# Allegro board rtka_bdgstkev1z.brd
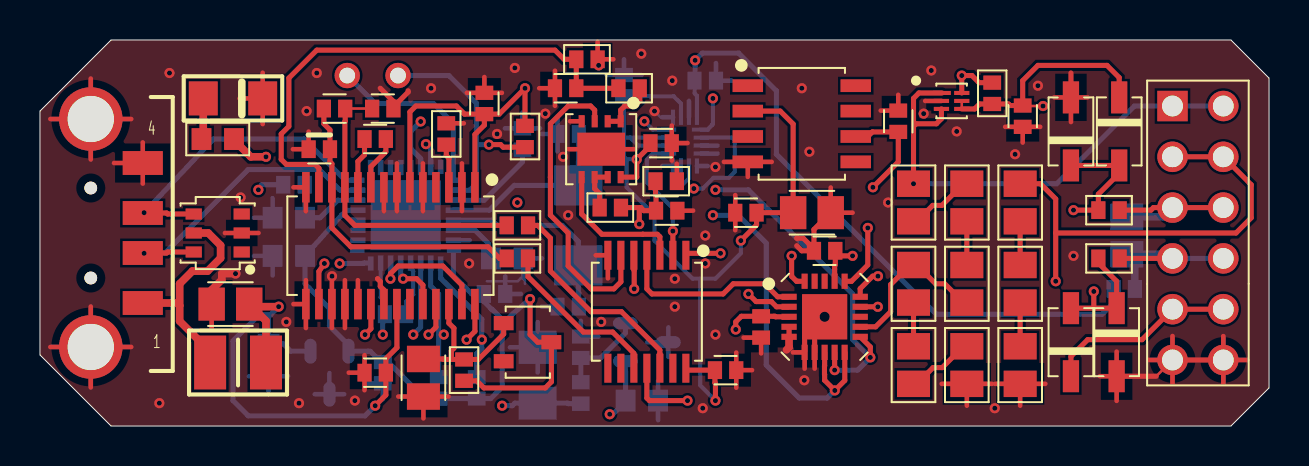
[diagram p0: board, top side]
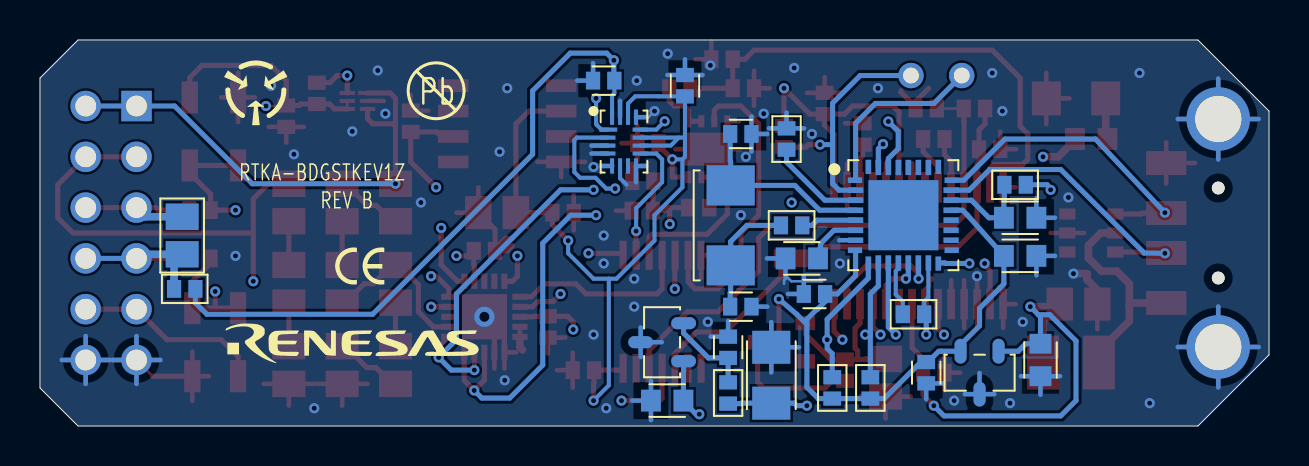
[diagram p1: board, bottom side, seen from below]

Outline 61.47 x 19.3 mm; copper layers: TOP, LAYER2, LAYER3, BOTTOM. Coordinates in mm from the lower left corner of the outline.
Outline path: 0,15.75 3.56,19.3 59.56,19.3 61.47,17.4 61.47,1.91 59.56,0 3.56,0 0,3.56 0,15.75

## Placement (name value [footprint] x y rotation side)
C1  -  [CAP_0402]  22.23 16.13 90 top
C2  -  [CAP_0402]  16.76 14.35 0 top
C3  -  [CAP_0603]  30.1 1.27 0 bottom
C4  -  [CAP_1206]  24.89 2.54 90 bottom
C5  -  [CAP_0402]  27.05 3.94 90 bottom
C6  -  [CAP_0402]  16.76 2.67 180 top
C7  -  [CAP_0805]  9.52 6.1 180 top
C8  -  [CAP_0805]  19.18 2.41 270 top
C9  -  [CAP_0402]  26.42 14.61 180 bottom
C11  -  [CAP_0603]  12.45 10.41 0 bottom
C12  -  [CAP_0603]  23.37 8.38 0 bottom
C13  -  [CAP_0402]  26.42 5.97 180 bottom
C14  -  [CAP_0402]  22.73 6.6 0 bottom
C15  -  [CAP_0603]  12.45 8.51 0 bottom
C16  -  [CAP_0402]  26.29 16.89 180 top
C17  -  [CAP_0402]  33.27 17.27 0 bottom
C18  -  [CAP_0402]  31.34 10.77 0 top
C19  -  [CAP_0402]  31.06 14.15 0 top
C20  -  [CAP_0402]  29.21 17.02 90 bottom
C21  -  [CAP_0805]  38.61 10.67 0 top
C22  -  [CAP_0402]  35.31 10.67 180 top
C23  -  [CAP_0402]  42.93 15.24 90 top
C25  -  [CAP_0402]  39.24 8.76 180 top
C26  -  [CAP_0603]  11.43 3.3 270 bottom
C27  -  [CAP_0402]  34.29 2.79 0 top
C28  -  [CAP_0402]  17.14 15.88 0 top
C29  -  [CAP_0402]  14.73 15.88 180 top
C30  -  [CAP_0402]  13.97 13.84 180 top
C31  -  [CAP_0402]  17.14 2.67 270 bottom
C32  -  [CAP_0402]  49.15 15.49 270 top
D1  -  [SOT23]  24.38 4.19 270 top
D2  -  [SOD123]  53.85 4.19 270 top
D3  -  [DIA_LED1206]  9.65 16.38 0 top
D4  -  [SOD123]  51.56 14.73 90 top
D5  -  [SOD123]  51.56 4.19 90 top
D6  -  [SOD123]  53.97 14.73 270 top
J1  -  [CON_USB_MOLEX_480371000]  2.54 9.65 180 top
J2  -  [CON_HDR_90151-3X12]  56.64 16 0 top
L1  -  [SM1210]  9.91 3.18 0 top
NOREF  -  []  -16.42 15.65 90 top
NOREF#2  -  []  27.15 8.12 0 top
NOREF#3  -  []  33.11 8.31 90 top
NOREF#4  -  []  29.76 11.47 0 top
NOREF#5  -  []  -12.83 34.42 0 top
NOREF#6  -  []  16.54 12.96 0 top
NOREF#7  -  []  -383.16 -115.32 0 top
NOREF#8  -  []  70.1 0 90 top
NOREF#9  -  []  28.15 8.22 0 top
NOREF#10  -  []  31.65 2.89 0 top
NOREF#11  -  []  26.92 8.03 90 top
NOREF#12  -  []  29.76 8.37 90 top
NOREF#13  -  []  28.15 3.21 90 top
NOREF#14  -  []  67.82 34.42 0 top
NOREF#15  -  []  -12.83 -4.95 0 top
NOREF#16  -  []  32.3 2.89 90 top
NOREF#17  -  []  28.11 11.51 0 top
NOREF#18  -  []  7.69 8.7 0 top
NOREF#19  -  []  20.71 8.79 90 top
NOREF#20  -  []  15.8 13.71 0 top
NOREF#21  -  []  15.9 11.29 90 top
NOREF#22  -  []  15.34 8.04 90 top
NOREF#23  -  []  64.52 17.4 90 top
NOREF#24  -  []  0 21.21 0 top
NOREF#25  -  []  7.69 8.7 90 top
NOREF#26  -  []  41.66 16.76 180 bottom
NOREF#27  -  []  50.67 16.76 180 bottom
NOREF#28  -  []  45.47 8 180 bottom
NOREF#29  -  []  52.45 3.05 180 bottom
P1  -  [PAD-50]  15.37 17.53 180 bottom
P2  -  [PAD-50]  17.91 17.53 180 bottom
R1  -  [RES_0402]  20.32 14.61 270 top
R2  -  [RES_0402]  27.05 1.65 270 bottom
R3  -  [RES_0402]  21.21 2.79 270 top
R4  -  [RES_0402]  23.88 10.03 180 top
R5  -  [RES_0402]  23.88 8.38 180 top
R6  -  [RES_0402]  36.07 4.95 90 top
R7  -  [RES_0402]  12.7 12.07 0 bottom
R8  -  [RES_0402]  24.26 14.48 270 top
R9  -  [RES_0402]  24.13 14.35 270 bottom
R10  -  [RES_0402]  23.88 10.03 180 bottom
R11  -  [RES_0402]  17.78 5.59 180 bottom
R12  -  [RES_0402]  19.94 1.91 270 bottom
R13  -  [RES_0402]  21.84 1.91 270 bottom
R14  -  [RES_0402]  29.46 16.89 0 top
R15  -  [RES_0402]  28.52 10.92 0 top
R16  -  [RES_0805]  43.69 11.18 90 top
R17  -  [RES_0603]  8.89 14.35 0 top
R18  -  [RES_0805]  46.35 11.18 90 top
R19  -  [RES_0805]  46.35 7.11 90 top
R20  -  [RES_0402]  47.62 16.64 270 top
R21  -  [RES_0805]  54.36 9.53 90 bottom
R22  -  [RES_0805]  43.69 7.11 90 top
R23  -  [RES_0805]  43.69 3.05 90 top
R24  -  [RES_0805]  46.35 3.05 90 top
R25  -  [RES_0805]  49.02 11.18 90 top
R26  -  [RES_0805]  49.02 7.11 90 top
R27  -  [RES_0805]  49.02 3.05 90 top
R28  -  [RES_0402]  53.47 10.79 0 top
R29  -  [RES_0402]  53.47 8.38 0 top
R30  -  [RES_0402]  54.23 6.86 180 bottom
RC16  -  [RES_0402]  27.36 18.34 180 top
RC18  -  [RES_0402]  31.32 12.24 180 top
U1  -  [UTQFN16_102X71_157]  32.26 14.22 180 bottom
U2  -  [SOT23-3]  30.35 4.19 90 bottom
U3  -  [DFN8_118X118_256_EP2]  28.07 13.84 270 top
U4  -  [TSSOP14_173_256_V2]  30.35 5.72 270 top
U5  -  [QFN20_157X157_197_EP]  39.24 5.46 0 top
U6  -  [SOIC8_150_50E]  38.1 15.11 0 top
U7  -  [QFN32_197X197_197_EPA2]  18.29 10.54 180 bottom
U8  -  [SOT457]  8.89 9.65 180 top
U9  -  [SOT23-3]  14.48 2.67 0 bottom
U10  -  [TSSOP28_173_256]  17.53 9.02 270 top
U11  -  [UTDFN6_47X39_157_A]  45.59 16.26 0 top
Y1  -  [XTAL_NX5032GA]  26.92 10.03 270 bottom

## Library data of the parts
C1 C6 C25 = SM_CAP: User Part Number: CAP_0402; alternate symbols: (SM0402_DELTA,SM0402RF,SM0402RD,SMC_C_0402); part number: SM_CAP_0402-H1044-00103-16V10,0.01UF,16V,10%,CAP_0402
C2 C5 C14 C16-C20 C22 C23 C27-C32 = SM_CAP: User Part Number: CAP_0402; alternate symbols: (SM0402_DELTA,SM0402RF,SM0402RD,SMC_C_0402); part number: SM_CAP_0402-H1044-00104-16V10,0.1UF,16V,10%,CAP_0402
C3 C11 C12 C26 = SM_CAP: User Part Number: CAP_0603; alternate symbols: (SM0603_DELTA,SM0603RF,SM0603RD,SMC_C_0603); part number: SM_CAP_0603-H1045-00105-16V20,1UF,16V,20%,CAP_0603
C4 = SM_CAP: User Part Number: CAP_1206; alternate symbols: (SM1206_DELTA,N_C1206,SM1206RF); part number: SM_CAP_1206-H1065-00106-16V10,10UF,16V,10%,CAP_1206
C7 = SM_CAP: User Part Number: CAP_0805; alternate symbols: (SM0805_DELTA,SM0805RF,SMC_C_0805); part number: SM_CAP_0805-GRM21BR71C475KA73L,4.7UF,16V,10%,CAP_0805
C8 = SM_CAP: User Part Number: CAP_0805; alternate symbols: (SM0805_DELTA,SM0805RF,SMC_C_0805); part number: SM_CAP_0805-H1046-00225-16V10,2.2UF,16V,10%,CAP_0805
C9 C13 = SM_CAP: User Part Number: CAP_0402; alternate symbols: (SM0402_DELTA,SM0402RF,SM0402RD,SMC_C_0402); part number: SM_CAP_0402-H1044-00100-50V10,10PF,50V,10%,CAP_0402
C15 = SM_CAP: User Part Number: CAP_0603; alternate symbols: (SM0603_DELTA,SM0603RF,SM0603RD,SMC_C_0603); part number: SM_CAP_0603-H1045-00334-25V10,0.33UF,25V,10%,CAP_0603
C21 = SM_CAP: User Part Number: CAP_0805; alternate symbols: (SM0805_DELTA,SM0805RF,SMC_C_0805); part number: SM_CAP_0805-C0805C106K8PACTU,10UF,10V,10%,CAP_0805
D1 = SM_SCHOTTKY: User Part Number: SOT23; part number: SM_SCHOTTKY_SINGLE-BAT54,SOT23
D2 D4-D6 = MMSD4148T1: User Part Number: SOD123; part number: MMSD4148T1_SOD123-MMSD4148T1,SOD123
D3 = SM_LED: User Part Number: DIA_LED1206; part number: SM_LED_SMD-597-3311-407,DIA_LED1206
J1 = USB_A: User Part Number: CON_USB_MOLEX_480371000; alternate symbols: (CON_USB_MOLEX_480371000_VER2,CON_USB_MOLEX_480371000); part number: USB_A_MOLEX1-48037-1000,CON_USB_MOLEX_480371000
J2 = HEADERS: User Part Number: CON_HDR_90151-3X12; part number: HEADERS_12-90151-3X12,CON_HDR_90151-3X12
L1 = IND1210: User Part Number: SM1210; part number: IND1210_SMD-IND1210-TBD,TBD,TBD,TBD,SM1210
P1 P2 = SINGLE: part number: SINGLE_THOLE-PAD_50-DNP,PAD-50
R1 R6 R11 R30 = SM_RES: User Part Number: RES_0402; part number: SM_RES_0402-H2510-00R00-1/16W,0,1/16W,0%,RES_0402
R2 R7 = SM_RES: User Part Number: RES_0402; part number: SM_RES_0402-H2510-01000-1/16W1,100,1/16W,1%,RES_0402
R3 = SM_RES: User Part Number: RES_0402; part number: SM_RES_0402-H2510-01001-1/16W1,1K,1/16W,1%,RES_0402
R4 R5 R14 R15 = SM_RES: User Part Number: RES_0402; part number: SM_RES_0402-H2510-049R9-1/16W1,49.9,1/16W,1%,RES_0402
R8 R9 R28 R29 = SM_RES: User Part Number: RES_0402; part number: SM_RES_0402-H2510-01002-1/16W1,10K,1/16W,1%,RES_0402
R10 = SM_RES: User Part Number: RES_0402; part number: SM_RES_0402-H2510-02210-1/16W1,221,1/16W,1%,RES_0402
R12 R13 R20 RC16 RC18 = SM_RES: User Part Number: RES_0402; part number: SM_RES_0402-H2510-04991-1/16W1,4.99K,1/16W,1%,RES_0402
R16 R22 R25 = SM_RES: User Part Number: RES_0805; part number: SM_RES_0805-H2512-02490-1/10W1,249,1/10W,1%,RES_0805
R17 = SM_RES: User Part Number: RES_0603; part number: SM_RES_0603-MCR03EZPFX3001,3K,1/10W,1%,RES_0603
R18 R23 R26 = SM_RES: User Part Number: RES_0805; part number: SM_RES_0805-H2512-01000-1/10W1,100,1/10W,1%,RES_0805
R19 R24 R27 = SM_RES: User Part Number: RES_0805; part number: SM_RES_0805-H2512-00010-1/10W1,1,1/10W,1%,RES_0805
R21 = SM_RES: User Part Number: RES_0805; part number: SM_RES_0805-H2512-04990-1/10W1,499,1/10W,1%,RES_0805
U1 = ISL23328: User Part Number: UTQFN16_102x71_157; part number: ISL23328_UTQFN16-ISL23328TFRUZ,UTQFN16_102X71_157
U2 = ISL21010: User Part Number: SOT23-3; part number: ISL21010_SOT23-3-ISL21010CFH341Z-TK,SOT23-3
U3 = ISL28233: User Part Number: DFN8_118X118_256_EP2; part number: ISL28233_TDFN8-ISL28233FRZ,DFN8_118X118_256_EP2
U4 = ISL28634: User Part Number: TSSOP14_173_256_V2; part number: ISL28634_TSSOP14-ISL28634FVZ,TSSOP14_173_256_V2
U5 = ISL43840: User Part Number: QFN20_157X157_197_EP; part number: ISL43840_20QFN-ISL43840IRZ,QFN20_157X157_197_EP
U6 = ISL21090: User Part Number: SOIC8_150_50E; part number: ISL21090_SOIC8-ISL21090BFB825Z-TK,SOIC8_150_50E
U7 = R5F10JBCANA: User Part Number: QFN32_197X197_197_EPA2; part number: R5F10JBCANA_32HWQFN-R5F10JBCANA,QFN32_197X197_197_EPA2
U8 = IP4220CZ6: User Part Number: SOT457; part number: IP4220CZ6_SOT457-IP4220CZ6,SOT457
U9 = ISL21010: User Part Number: SOT23-3; part number: ISL21010_SOT23-3-ISL21010CFH333Z-TK,SOT23-3
U10 = ISL26104: User Part Number: TSSOP28_173_256; part number: ISL26104_TSSOP-ISL26104AVZ,TSSOP28_173_256
U11 = ISL54054: User Part Number: UTDFN6_47X39_157_A; part number: ISL54054_UTDFN6-ISL54054IRUZ,UTDFN6_47X39_157_A
Y1 = SM_CRYSTAL: User Part Number: XTAL_NX5032GA; part number: SM_CRYSTAL_SM-NX5032GA-48.000M-LN-CD-1,XTAL_NX5032GA

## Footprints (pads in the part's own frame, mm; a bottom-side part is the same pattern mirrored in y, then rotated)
CAP_0402
  rect 0.711x0.889 smd: 1(-0.533,0) 2(0.533,0)
CAP_0603
  rect 0.991x1.092 smd: 1(-0.813,0) 2(0.813,0)
CAP_0805
  rect 1.321x1.651 smd: 1(-0.94,0) 2(0.94,0)
CAP_1206
  rect 1.651x1.905 smd: 1(-1.397,0) 2(1.397,0)
CON_HDR_90151-3X12
  rect 1.524x1.524 hole 1.041: 1(0,0)
  round 1.524 hole 1.041: 2(2.54,0) 3(0,-2.54) 4(2.54,-2.54) 5(0,-5.08) 6(2.54,-5.08) 7(0,-7.62) 8(2.54,-7.62) 9(0,-10.16) 10(2.54,-10.16) 11(0,-12.7) 12(2.54,-12.7)
CON_USB_MOLEX_480371000
  round 0.635 hole 1.194 unplated: (0,2.25) (0,-2.25)
  rect 2.007x1.194 smd: 1(-2.6,3.5) 2(-2.6,1) 3(-2.6,-1) 4(-2.6,-3.5)
  round 3.175 hole 2.311: M1(0,5.7) M2(0,-5.7)
DFN8_118X118_256_EP2
  rect 0.61x0.305 smd: 1(-1.397,0.975) 2(-1.397,0.325) 3(-1.397,-0.325) 4(-1.397,-0.975) 5(1.397,-0.975) 6(1.397,-0.325) 7(1.397,0.325) 8(1.397,0.975)
  rect 1.651x2.388 smd: 9(0,0)
DIA_LED1206
  rect 1.448x1.702 smd: 1(-1.486,0) 2(1.486,0)
PAD-50
  round 1.27 hole 0.787: 1(0,0)
QFN20_157X157_197_EP
  rect 0.762x0.305 smd: 1(-1.778,1.001) 2(-1.778,0.5) 3(-1.778,0) 4(-1.778,-0.5) 5(-1.778,-1.001) 11(1.778,-1.001) 12(1.778,-0.5) 13(1.778,0) 14(1.778,0.5) 15(1.778,1.001)
  rect 0.305x0.762 smd: 6(-1.001,-1.778) 7(-0.5,-1.778) 8(0,-1.778) 9(0.5,-1.778) 10(1.001,-1.778) 16(1.001,1.778) 17(0.5,1.778) 18(0,1.778) 19(-0.5,1.778) 20(-1.001,1.778)
  rect 2.261x2.261 smd: 21(0,0)
QFN32_197X197_197_EPA2
  rect 0.711x0.279 smd: 1(-2.418,1.75) 8(-2.418,-1.75) 17(2.418,-1.75) 24(2.418,1.75)
  rect 0.762x0.279 smd: 2(-2.388,1.252) 3(-2.388,0.752) 4(-2.388,0.249) 5(-2.388,-0.249) 6(-2.388,-0.752) 7(-2.388,-1.252) 18(2.388,-1.252) 19(2.388,-0.752) 20(2.388,-0.249) 21(2.388,0.249) 22(2.388,0.752) 23(2.388,1.252)
  rect 0.279x0.711 smd: 9(-1.75,-2.418) 16(1.75,-2.418) 25(1.75,2.418) 32(-1.75,2.418)
  rect 0.279x0.762 smd: 10(-1.252,-2.388) 11(-0.752,-2.388) 12(-0.249,-2.388) 13(0.249,-2.388) 14(0.752,-2.388) 15(1.252,-2.388) 26(1.252,2.388) 27(0.752,2.388) 28(0.249,2.388) 29(-0.249,2.388) 30(-0.752,2.388) 31(-1.252,2.388)
  rect 3.505x3.505 smd: 33(0,0)
RES_0402
  rect 0.711x0.889 smd: 1(-0.533,0) 2(0.533,0)
RES_0603
  rect 0.991x1.092 smd: 1(-0.813,0) 2(0.813,0)
RES_0805
  rect 1.321x1.651 smd: 1(-0.94,0) 2(0.94,0)
SM1210
  rect 1.6x2.692 smd: 1(-1.397,0) 2(1.397,0)
SOD123
  rect 1.6x0.813 smd: 1(-1.702,0) 2(1.702,0)
SOIC8_150_50E
  rect 1.524x0.635 smd: 1(-2.7,1.905) 2(-2.7,0.635) 3(-2.7,-0.635) 4(-2.7,-1.905) 5(2.7,-1.905) 6(2.7,-0.635) 7(2.7,0.635) 8(2.7,1.905)
SOT23
  rect 0.711x0.991 smd: 1(-0.953,-1.194) 2(0.953,-1.194) 3(0,1.194)
SOT23-3
  oval 0.61x1.245 smd: 1(-0.95,-1.075) 2(0.95,-1.075) 3(0,1.075)
SOT457
  rect 0.813x0.559 smd: 1(-1.2,0.95) 2(-1.2,0) 3(-1.2,-0.95) 4(1.2,-0.95) 5(1.2,0) 6(1.2,0.95)
TSSOP14_173_256_V2
  rect 1.448x0.356 smd: 1(-2.825,1.95) 2(-2.825,1.3) 3(-2.825,0.65) 4(-2.825,0) 5(-2.825,-0.65) 6(-2.825,-1.3) 7(-2.825,-1.95) 8(2.825,-1.95) 9(2.825,-1.3) 10(2.825,-0.65) 11(2.825,0) 12(2.825,0.65) 13(2.825,1.3) 14(2.825,1.95)
TSSOP28_173_256
  rect 1.524x0.381 smd: 1(-2.921,4.227) 2(-2.921,3.576) 3(-2.921,2.926) 4(-2.921,2.276) 5(-2.921,1.626) 6(-2.921,0.975) 7(-2.921,0.325) 8(-2.921,-0.325) 9(-2.921,-0.975) 10(-2.921,-1.626) 11(-2.921,-2.276) 12(-2.921,-2.926) 13(-2.921,-3.576) 14(-2.921,-4.227) 15(2.921,-4.227) 16(2.921,-3.576) 17(2.921,-2.926) 18(2.921,-2.276) 19(2.921,-1.626) 20(2.921,-0.975) 21(2.921,-0.325) 22(2.921,0.325) 23(2.921,0.975) 24(2.921,1.626) 25(2.921,2.276) 26(2.921,2.926) 27(2.921,3.576) 28(2.921,4.227)
UTDFN6_47X39_157_A
  rect 0.889x0.203 smd: 1(-0.483,0.399)
  rect 0.762x0.203 smd: 2(-0.508,0) 3(-0.508,-0.399) 4(0.508,-0.399) 5(0.508,0) 6(0.508,0.399)
UTQFN16_102X71_157
  rect 0.889x0.203 smd: 1(-0.787,0.598)
  rect 0.762x0.203 smd: 2(-0.813,0.199) 3(-0.813,-0.199) 4(-0.813,-0.598) 9(0.813,-0.598) 10(0.813,-0.199) 11(0.813,0.199) 12(0.813,0.598)
  rect 0.203x0.762 smd: 5(-0.598,-1.219) 6(-0.199,-1.219) 7(0.199,-1.219) 8(0.598,-1.219) 13(0.598,1.219) 14(0.199,1.219) 15(-0.199,1.219) 16(-0.598,1.219)
XTAL_NX5032GA
  rect 2.007x2.413 smd: 1(-2,0) 2(2,0)

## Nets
+3.3V: C1.1(A) C14.1(A) C15.2(B) C17.1(A) C31.1(A) D1.3(CATS) R3.2(B) R8.1(A) R12.2(B) R13.2(B) R30.2(B) U1.16 U7.8 U7.21 U9.2(VOUT) U10.1 U10.6
+5V: C3.1(A) C6.1(A) C7.1(A) C19.1(A) C20.1(A) C21.1(A) C22.1(A) C25.1(A) C26.1(A) C27.1(A) C32.1(A) D5.1(CAT) D6.1(CAT) J2.9(IN1) J2.10(IN1) L1.2(B) R7.1(A) R17.2(B) R20.2(B) U1.10 U1.11 U1.14 U2.1(VIN) U3.8 U4.14 U5.17 U6.2 U9.1(VIN) U10.22 U11.4 U11.5
GND: C1.2(B) C3.2(B) C4.2(B) C5.2(B) C6.2(B) C7.2(B) C8.2(B) C9.2(B) C11.1(A) C12.2(B) C13.2(B) C14.2(B) C15.1(A) C16.2(B) C17.2(B) C18.2(B) C19.2(B) C20.2(B) C21.2(B) C22.2(B) C23.2(B) C25.2(B) C26.2(B) C27.2(B) C28.2(B) C30.2(B) C31.2(B) C32.2(B) D2.2(AN) D3.2(B) D4.2(AN) J1.4 J1.M1 J1.M2 J2.11(IN1) J2.12(IN1) R1.1(A) R6.1(A) R9.1(A) R24.1(A) R27.1(A) RC16.1(A) RC18.1(A) U1.3 U1.4 U1.5 U1.6 U1.8 U1.13 U1.15 U2.3(GND) U3.4 U3.9(EP) U4.7 U5.4 U5.5 U5.6 U5.7 U5.21 U6.4 U7.7 U8.2 U9.3(GND) U10.2 U10.5 U10.7 U10.8 U10.14 U10.15 U10.17 U10.18 U10.19 U10.21 U11.2
ADDA: U5.8 U5.10 U7.31
ADDB: U5.9 U5.11 U7.30
CS: U7.13 U10.24
IN: R20.1(A) U7.11 U11.6
IN2: C16.1(A) R14.1(A) RC16.2(B) U10.13
IN3: C18.1(A) R15.2(B) RC18.2(B) U10.16
SCL: R13.1(A) U1.2 U7.9
SCLK: U7.14 U10.27
SDA: R12.1(A) U1.1 U7.10
SDI: U7.16 U10.25
SDO/RDY: R11.2(B) U7.15 U10.28
UNNAMED_1_1210IND_I97_A: J1.1 L1.1(A) U8.5
UNNAMED_1_HEADERS_I279_IN1: J2.1(IN1) J2.2(IN1) R16.2(B) U11.1 U11.3
UNNAMED_1_HEADERS_I281_IN1: J2.3(IN1) J2.4(IN1) R25.2(B) U5.2
UNNAMED_1_HEADERS_I283_IN1: J2.5(IN1) J2.6(IN1) R21.2(B) R28.2(B)
UNNAMED_1_HEADERS_I285_IN1: J2.7(IN1) J2.8(IN1) R21.1(A) R29.2(B) R30.1(A)
UNNAMED_1_IP4220CZ6_I167_4: J1.3 U7.24 U8.4
UNNAMED_1_IP4220CZ6_I167_6: J1.2 U7.23 U8.6
UNNAMED_1_ISL23328_I318_9: U1.9 U4.2
UNNAMED_1_ISL23328_I318_12: U1.12 U4.1
UNNAMED_1_ISL26104_I314_10: C2.1(A) U10.10
UNNAMED_1_ISL28233_I317_1: R14.2(B) U3.1 U3.2
UNNAMED_1_ISL28233_I317_3: U3.3 U4.6
UNNAMED_1_ISL28233_I317_5: U3.5 U4.3
UNNAMED_1_ISL28233_I317_6: R15.1(A) U3.6 U3.7
UNNAMED_1_ISL28634_I315_4: U4.4 U5.1
UNNAMED_1_ISL28634_I315_5: U4.5 U5.14
UNNAMED_1_ISL43840_I225_15: R6.2(B) U5.3 U5.15
UNNAMED_1_MMSD4148T1_I291_AN: D4.1(CAT) D6.2(AN) R28.1(A) U5.16
UNNAMED_1_MMSD4148T1_I302_CAT: D2.1(CAT) D5.2(AN) R29.1(A) U5.20
UNNAMED_1_R5F10JBCANA_I307_1: P1.1(P) U7.1
UNNAMED_1_R5F10JBCANA_I307_2: P2.1(P) R8.2(B) U7.2
UNNAMED_1_R5F10JBCANA_I307_3: R9.2(B) U7.3
UNNAMED_1_R5F10JBCANA_I307_5: R10.2(B) U7.5
UNNAMED_1_R5F10JBCANA_I307_6: C12.1(A) U7.6
UNNAMED_1_R5F10JBCANA_I307_12: R11.1(A) U7.12
UNNAMED_1_R5F10JBCANA_I307_22: C11.2(B) R7.2(B) U7.22
UNNAMED_1_SMCAP_I18_B: C2.2(B) U10.9
UNNAMED_1_SMCAP_I21_A: C8.1(A) D1.1(ANS) R3.1(A) U10.26
UNNAMED_1_SMCAP_I197_A: C4.1(A) R2.2(B) U10.20
UNNAMED_1_SMCAP_I319_A: C28.1(A) C29.1(A) R4.2(B) U10.11
UNNAMED_1_SMCAP_I319_B: C29.2(B) C30.1(A) R5.2(B) U10.12
UNNAMED_1_SMCAP_I323_A: C23.1(A) U4.11 U6.6
UNNAMED_1_SMCAP_I358_A: C9.1(A) U7.4 Y1.1(A)
UNNAMED_1_SMCAP_I359_A: C13.1(A) R10.1(A) Y1.2(B)
UNNAMED_1_SMLED_I99_A: D3.1(A) R17.1(A)
UNNAMED_1_SMRES_I15_B: R1.2(B) U10.3
UNNAMED_1_SMRES_I227_A: R5.1(A) U4.10
UNNAMED_1_SMRES_I228_A: R4.1(A) U4.12
UNNAMED_1_SMRES_I262_A: R18.1(A) R19.2(B)
UNNAMED_1_SMRES_I262_B: R16.1(A) R18.2(B)
UNNAMED_1_SMRES_I264_A: R19.1(A) R22.2(B) U5.12
UNNAMED_1_SMRES_I265_A: R22.1(A) R23.2(B)
UNNAMED_1_SMRES_I266_A: R23.1(A) R24.2(B)
UNNAMED_1_SMRES_I268_A: R25.1(A) R26.2(B)
UNNAMED_1_SMRES_I269_A: R26.1(A) R27.2(B)
VREF: C5.1(A) R2.1(A) U2.2(VOUT)

Pads without a net: D1 2; U1 7; U4 8 9 13; U5 13 18 19; U6 1 3 5 7 8; U7 17 18 19 20 25 26 27 28 29 32 33; U8 1 3; U10 4 23

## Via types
v1: diameter 0.508, hole 0.254, TOP to BOTTOM, 96 vias
v2: diameter 1.016, hole 0.508, TOP to BOTTOM, 1 via

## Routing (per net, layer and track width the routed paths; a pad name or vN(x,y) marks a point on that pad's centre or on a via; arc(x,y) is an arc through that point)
+3.3V: length 106.9
  TOP w0.254: C1.1 21.23,15.6 20.83,16 18.8,16 18.5,15.71 U10.6 ; C1.1 22.96,15.6 v1(24.26,16.89) R8.1 ; C1.1 22.23,15.05 21.75,14.58 U10.1 ; R3.2 21.84,2.26 22.2,1.91 25.27,1.91 25.58,2.21 D1.3 24.89,4.19 24.51,4.57 v1(24.51,6.35)
  LAYER3 w0.254: v1(32.77,18.29) 31.46,18.29 30.41,17.19 30.11,16.89 26.92,16.89 ; v1(24.51,6.35) 24.51,10.03 26.92,12.45 26.92,16.89 ; 26.92,16.89 v1(24.26,16.89)
  BOTTOM w0.127: 20.68,8.79 20.68,8.79 U7.8 ; U7.21 15.9,10.79
  BOTTOM w0.203: U1.16 32.86,16.52 32.74,16.64 C17.1
  BOTTOM w0.254: 23.11,5.08 23.62,5.59 v1(24.51,6.35) ; 23.11,5.08 23.11,1.94 22.54,1.37 R13.2 R12.2 19.24,1.37 17.41,3.2 C31.1 17.06,3.2 16.52,3.74 16.39,3.74 16.39,3.74 U9.2 15.43,4.06 14.48,5.01 14.48,5.89 13.46,6.9 13.26,7.11 C15.2 15.08,10.54 15.33,10.79 15.9,10.79 ; 23.11,5.08 23.11,5.33 22.61,5.84 22.58,5.84 22.2,6.22 C14.1 21.59,6.6 20.68,7.52 20.68,8.79 ; R30.2 53.7,6.16 53.12,5.59 44.83,5.59 36.83,13.59 36.83,16.76 34.95,18.65 33.13,18.65 v1(32.77,18.29) 32.77,17.3 C17.1
+5V: length 171.6
  TOP w0.127: U6.2 35.56,15.75 ; v1(50.16,16) 49.17,16 C32.1 ; 39.78,8.06 39.78,7.87 39.74,7.84 ; U4.14 32.3,2.79 ; U11.5 U11.4
  TOP w0.254: 35.56,15.75 37.02,15.75 37.67,15.1 C21.1 C22.1 35.84,10.06 v1(35.05,9.27) ; U11.4 46.74,15.86 46.99,16.1 R20.2 48.44,16.1 48.51,16.03 C32.1 49.15,17.27 49.91,18.03 53.37,18.03 53.97,17.42 D6.1 ; v1(33.78,1.27) 33.78,2.13 33.76,2.16 C27.1 32.3,2.79 ; C19.1 30.53,14.02 v1(29.84,13.34) 29.84,12.45 U3.8 ; v1(16.76,1.02) 17.3,1.55 C6.1 17.3,3.37 17.85,3.92 U10.22 ; v1(40.64,8.51) 40.03,8.51 C25.1 39.78,8.06 39.74,8.03 U5.17 ; D5.1 51.56,3.48 52.4,4.32 55.12,4.32 J2.9 J2.10
  TOP w0.381: 10.59,5.97 v1(11.94,5.97) ; 10.59,5.97 C7.1 ; 10.59,5.97 11.3,5.26 L1.2 ; R17.2 9.7,14.3 10.54,13.46 v1(11.3,13.46)
  LAYER2 w0.254: v1(16.76,1.02) 17.27,0.51 27.9,0.51 27.99,0.59 v1(28.49,0.59) 28.81,0.27 33.49,0.27 33.78,0.57 v1(33.78,1.27)
  LAYER3 w0.254: 47.68,13.51 55.35,5.84 J2.9 ; 47.68,13.51 42.67,8.51 ; 47.68,13.51 v1(50.16,16) ; 42.67,8.51 v1(40.64,8.51) ; 42.67,8.51 43.31,7.87 43.31,2.54 41.68,0.91 34.14,0.91 v1(33.78,1.27) ; v1(11.94,5.97) 11.94,8.76 10.92,9.78 v1(10.92,11.81) 11.3,12.19 v1(11.3,13.46)
  BOTTOM w0.203: 29.52,14.42 29.92,14.02 U1.10 ; 29.52,14.42 29.21,14.42 ; 29.52,14.42 U1.11 ; 29.34,13.34 29.34,11.94 30.73,10.54 30.73,9.27 32.64,7.37 33.02,7.37 ; 29.34,13.34 29.21,13.46 29.21,14.42 ; 29.34,13.34 v1(29.84,13.34) ; 33.02,7.37 33.02,2.03 v1(33.78,1.27) ; 33.02,7.37 33.78,7.37 35.05,8.64 v1(35.05,9.27) ; 29.21,14.42 C20.1 30.54,16.48 30.55,16.49 31.69,16.49 32.06,16.13 U1.14
  BOTTOM w0.254: v1(10.92,11.81) 11.09,12.07 R7.1 ; v1(28.49,0.59) 28.66,0.59 29.29,1.22 C3.1 29.29,2.74 29.28,2.75 U2.1 ; v1(16.76,1.02) 16.26,0.51 10.41,0.51 9.65,1.27 9.65,4.25 10.96,5.56 11.53,5.56 ; 11.53,5.56 11.43,5.46 C26.1 12.17,4.11 12.54,3.74 U9.1 ; 11.53,5.56 v1(11.94,5.97)
GND: length 254.7
  TOP w0.127: 55.83,2.49 J2.11
  TOP w0.229: D2.2 53.85,3.72 ; D2.2 53.01,2.49 ; D2.2 53.85,1.26 ; 25.76,16.01 C16.2 ; C16.2 24.97,16.89 ; C16.2 25.76,17.77 ; 15.25,7.29 U10.18 15.25,4.9 ; 27.89,19.22 RC16.1 28.68,18.34 ; J2.11 56.64,4.5 ; J2.11 55.45,3.3 ; J2.11 56.64,2.11 ; 13.3,4.9 U10.15 ; U10.15 12.68,6.1 ; U10.15 13.3,7.29 ; J1.M2 4.56,15.35 ; J1.M2 2.54,13.33 ; J1.M2 0.52,15.35 ; J1.M2 2.54,17.37 ; 35.4,12.46 U6.4 ; U6.4 34.21,13.21 ; U6.4 36.59,13.21 ; C1.2 23.1,16.66 ; C1.2 22.23,17.45 ; C1.2 21.35,16.66 ; 29.69,13.84 U3.9 26.44,13.84 ; 39.55,11.93 C21.2 40.64,10.67 ; 51.56,15.2 D4.2 ; D4.2 52.4,16.43 ; D4.2 50.72,16.43 ; 19.15,10.74 U10.5 19.15,13.13 ; 38.74,2.87 U5.7 ; C27.2 35.61,2.79 ; C27.2 34.82,3.67 ; C27.2 34.82,1.92 ; C32.2 50.03,14.96 ; C32.2 49.15,14.17 ; C32.2 48.27,14.96 ; R24.1 47.61,2.11 ; R24.1 45.1,2.11 ; R24.1 46.35,1.02 ; 31.6,13.27 C19.2 ; C19.2 31.6,15.02 ; C19.2 32.39,14.15 ; 12.65,13.84 C30.2 13.44,14.72 ; 59.18,2.11 J2.12 ; J2.12 60.38,3.3 ; J2.12 59.18,4.5 ; 14.6,7.29 U10.17 14.6,4.9 ; 44.27,16.26 U11.2 ; 2.54,1.93 J1.M1 ; J1.M1 4.56,3.95 ; J1.M1 2.54,5.97 ; J1.M1 0.52,3.95 ; 34.77,9.79 C22.2 34.77,11.54 ; J1.4 5.14,14.18 ; J1.4 5.14,12.12 ; J1.4 3.7,13.15 ; 16.23,1.79 C6.2 ; C6.2 15.44,2.67 ; C6.2 16.23,3.54 ; 38.24,2.87 U5.6 37.66,3.68 ; 13.3,10.74 U10.14 12.68,11.94 ; 26.51,15.24 U3.4 ; RC18.1 31.85,13.12 ; U10.19 15.9,7.29 ; 8.59,4.84 C7.2 ; C8.2 20.43,1.47 ; C8.2 19.18,0.38 ; C8.2 17.92,1.47 ; 35.19,4.42 R6.1 36.07,3.63 ; 42.05,15.77 C23.2 42.93,16.56 ; 21.1,10.74 U10.2 21.1,13.13 ; 49.02,1.02 R27.1 ; R27.1 47.76,2.11 ; R27.1 50.28,2.11 ; 17.85,10.74 U10.7 17.85,13.13 ; 27.79,8.54 U4.7 28.4,7.38 ; 9.25,9.65 U8.2 10.93,9.65 ; 17.2,10.74 U10.8 ; 11.14,15.1 D3.2 ; D3.2 9.98,16.38 ; D3.2 11.14,17.67 ; R1.1 21.2,15.14 ; C18.2 32.66,10.77
  TOP w0.254: 17.68,15.96 18.41,16.7 18.41,16.76 ; 17.68,15.96 17.68,16.23 17.02,16.89 ; 17.68,15.96 C28.2 ; U5.7 38.74,4.96 ; 38.74,4.96 v2(39.24,5.46) ; 38.74,4.96 38.24,4.46 U5.6 ; 16.88,7.37 16.88,7.36 17.02,7.23 17.02,6.98 17.2,6.8 U10.21 ; 38.71,8.85 C25.2 38.1,8.76 37.85,9.02 ; 38.71,8.85 38.17,9.39 37.86,9.39 37.85,9.4 ; 38.71,8.85 38.71,9.83 C21.2 ; U5.4 U5.5 ; J2.11 J2.12 ; D2.2 55.83,2.49 ; D4.2 51.56,17.65
  TOP w0.381: C7.2 8.59,6.81 9.09,7.32 9.09,7.62 v1(9.78,7.62) ; U5.5 37.46,3.94 37.34,3.81
  LAYER2 w0.229: 56.64,2.11 J2.11 ; J2.11 57.84,3.3 ; J2.11 55.45,3.3 ; J2.11 56.64,4.5 ; 59.18,2.11 J2.12 ; J2.12 60.38,3.3 ; J2.12 57.99,3.3 ; J2.12 59.18,4.5 ; 0.52,15.35 J1.M2 ; J1.M2 2.54,17.37 ; J1.M2 4.56,15.35 ; J1.M2 2.54,13.33 ; J1.M1 4.56,3.95 ; J1.M1 2.54,5.97 ; J1.M1 0.52,3.95 ; J1.M1 2.54,1.93
  LAYER3 w0.229: 57.99,3.3 J2.12 ; J2.12 60.38,3.3 ; J2.12 59.18,2.11 ; J2.12 59.18,4.5 ; J1.M1 2.54,5.97 ; J1.M1 2.54,1.93 ; J1.M1 0.52,3.95 ; J1.M1 4.56,3.95 ; J2.11 57.84,3.3 ; J2.11 56.64,4.5 ; J2.11 56.64,2.11 ; J2.11 55.45,3.3 ; J1.M2 4.56,15.35 ; J1.M2 2.54,13.33 ; J1.M2 0.52,15.35 ; J1.M2 2.54,17.37
  BOTTOM w0.127: 24.26,7.11 24.26,7.28 24.13,7.4 24.05,7.4 23.89,7.24 22.35,7.24 ; v1(30.73,15.75) 31.05,15.43 31.65,15.43 U1.13
  BOTTOM w0.203: 32.13,12.07 32.46,12.39 U1.6
  BOTTOM w0.229: U2.3 31.43,4.93 ; U2.3 30.37,4.19 ; U2.3 31.43,3.45 ; U7.7 21.49,9.29 ; 2.54,1.93 J1.M1 ; J1.M1 4.56,3.95 ; J1.M1 2.54,5.97 ; J1.M1 0.52,3.95 ; 23.27,7.48 C14.2 24.05,6.6 ; J2.11 56.64,4.5 ; J2.11 56.64,2.11 ; J2.11 55.45,3.3 ; J2.11 57.84,3.3 ; 2.54,13.33 J1.M2 ; J1.M2 2.54,17.37 ; J1.M2 4.56,15.35 ; J1.M2 0.52,15.35 ; 11.63,11.39 C11.1 10.71,10.41 ; U9.3 15.22,1.59 ; U9.3 14.48,2.65 ; U9.3 13.74,1.59 ; 10.71,8.51 C15.1 11.63,7.53 ; 23.51,3.94 C4.2 ; C4.2 24.89,2.68 ; C4.2 24.89,5.19 ; 24.18,7.4 C12.2 25.11,8.38 ; C3.2 31.84,1.27 ; C3.2 30.91,0.29 ; C3.2 30.91,2.25 ; 31.13,15.44 U1.13 ; 31.66,12.19 U1.8 31.13,13 ; 25.09,14.61 C9.2 ; C9.2 25.88,15.48 ; C9.2 25.88,13.73 ; U1.5 33.39,13 ; 27.93,4.47 C5.2 27.05,5.26 ; U1.4 33.88,13.63 ; 11.43,1.56 C26.2 ; C26.2 10.45,2.49 ; C26.2 12.41,2.49 ; 16.27,2.13 C31.2 17.14,1.35 ; 34.6,17.27 C17.2 33.81,18.15 ; C20.2 30.09,17.55 ; C20.2 29.21,18.34 ; C20.2 28.33,17.55 ; U1.15 32.46,16.26 ; U1.3 33.88,14.02 ; 23.25,14.88 R9.1 ; R9.1 24.13,15.67 ; R9.1 25.01,14.88 ; J2.12 60.38,3.3 ; J2.12 57.99,3.3 ; J2.12 59.18,4.5 ; J2.12 59.18,2.11 ; 25.09,5.97 C13.2
  vias: v1(5.97,1.14) v1(6.48,17.65) v1(10.03,11.43) v1(12.32,5.21) v1(12.95,1.14) v1(13.34,15.75) v1(13.84,17.65) v1(14.61,7.49) v1(15.75,1.27) v1(19.56,16.89) v1(21.46,8.13) v1(22.86,14.61) v1(23.75,17.91) v1(25.27,15.62) v1(26.16,13.46) v1(26.42,10.54) v1(27.94,18.03) v1(28.07,5.21) v1(30.07,18.62) v1(31.62,17.27) v1(31.75,7.37) v1(31.75,5.97) v1(33.15,0.89) v1(33.27,9.53) v1(33.27,8.13) v1(33.78,12.95) v1(33.78,4.57) v1(38.1,16.89) v1(38.23,2.29) v1(38.48,13.72) v1(42.42,11.18) v1(44.2,15.62) v1(44.58,17.78) v1(45.85,14.73) v1(47.75,0.89) v1(48.77,13.59) v1(49.91,17.02) v1(51.69,8.51)
ADDA: length 34.9
  TOP w0.254: U5.8 39.24,3.01 39.24,3 39.24,2.58 39.24,2.58 39.24,2.29 v1(39.75,1.78) 40.25,2.28 40.25,3.68 U5.10
  LAYER2 w0.254: v1(19.3,14.1) 20.7,12.7 25.53,12.7 27.33,10.9 33.3,10.9 v1(33.66,10.54)
  BOTTOM w0.127: U7.31 19.54,12.93
  BOTTOM w0.254: v1(19.3,14.1) 19.54,13.86 19.54,12.93 ; v1(33.66,10.54) 34.93,10.54 36.32,9.14 36.32,3.05 37.97,1.4 39.37,1.4 v1(39.75,1.78)
ADDB: length 35.6
  TOP w0.254: U5.9 v1(39.74,2.79) ; U5.11 41.53,3.95 v1(41.53,3.43)
  LAYER2 w0.254: v1(19.04,15.23) 24.4,15.23 25.65,13.97 31.62,13.97 v1(33.78,11.81)
  BOTTOM w0.127: 19.04,12.93 U7.30
  BOTTOM w0.254: 19.04,12.93 19.04,13.37 18.54,13.87 18.54,14.73 v1(19.04,15.23) ; v1(39.74,2.79) 40.89,2.79 v1(41.53,3.43) 40.64,4.32 40.64,6.6 35.43,11.81 v1(33.78,11.81)
CS: length 2.9
  TOP w0.254: U10.24 19.15,7.05 18.83,7.37 v1(18.16,7.37)
  BOTTOM w0.127: U7.13 18.04,8.15
  BOTTOM w0.254: 18.04,8.15 18.04,7.49 v1(18.16,7.37)
IN: length 40.8
  TOP w0.254: U11.6 v1(46.1,17.53) 46.61,17.53 46.96,17.17 R20.1
  LAYER2 w0.254: v1(46.1,17.53) 45.21,16.64 43.43,16.64 29.34,2.54 20.7,2.54 v1(18.67,4.57)
  BOTTOM w0.127: 19.04,8.15 U7.11
  BOTTOM w0.254: v1(18.67,4.57) 19.04,4.94 19.04,8.15
IN2: length 25.9
  TOP w0.254: R14.1 C16.1 RC16.2 26.21,18.34 25.76,18.8 13.84,18.8 12.45,17.4 12.45,14.99 12.06,14.6 12.06,13.34 12.32,13.08 13.76,13.08 13.95,12.89 U10.13
IN3: length 24.3
  TOP w0.254: 30.05,10.92 30.2,10.77 C18.1 30.81,11.52 30.78,11.54 RC18.2 ; 30.05,10.92 29.97,10.85 v1(29.97,10.1) ; 30.05,10.92 R15.2 ; v1(14.22,8.13) 13.95,7.73 U10.16
  LAYER2 w0.254: v1(23.88,11.18) 25.31,9.74 29.61,9.74 v1(29.97,10.1)
  LAYER3 w0.254: v1(23.88,11.18) 16.76,11.18 14.22,8.64 v1(14.22,8.13)
SCL: length 26.1
  LAYER3 w0.254: v1(32.7,11.87) 25.15,4.32 v1(22.1,4.32)
  BOTTOM w0.127: 20.04,8.15 20.04,8.15 U7.9
  BOTTOM w0.203: v1(32.7,11.87) 33.15,11.87 33.69,12.41 34.46,12.41 34.74,12.7 34.74,14.3 34.62,14.42 U1.2
  BOTTOM w0.254: 20.04,8.15 20.04,7.39 22.1,5.33 v1(22.1,4.32) 22.1,3.87 21.84,3.62 R13.1
SCLK: length 6.1
  TOP w0.254: U10.27 21.1,7.05 20.15,8 17.91,8 17.53,7.62 v1(17.53,7.37)
  BOTTOM w0.254: v1(17.53,7.37) 17.53,7.58 17.53,7.58 17.53,7.75 17.53,7.89 U7.14 17.54,8.15
SDA: length 27.8
  LAYER3 w0.254: v1(33.66,16.38) 25.78,8.51 25.78,6.22 25.02,5.46 21.08,5.46 v1(20.19,4.57)
  BOTTOM w0.127: U7.10 19.54,8.15 ; 19.94,4.57 v1(20.19,4.57)
  BOTTOM w0.203: U1.1 33.39,14.82 33.62,15.06 33.62,15.08 33.66,15.11 v1(33.66,16.38)
  BOTTOM w0.254: R12.1 19.94,6.6 19.54,7 19.54,8.15
SDI: length 9.5
  TOP w0.254: v1(19.43,4.57) 19.8,4.94 U10.25
  LAYER2 w0.254: v1(14.99,8.13) 17.14,5.46 18.8,5.46 19.43,4.83 v1(19.43,4.57)
  BOTTOM w0.127: 16.54,8.15 16.54,8.15 U7.16
  BOTTOM w0.254: v1(14.99,8.13) 16.18,8.13 16.21,8.15 16.54,8.15
SDO/RDY: length 10.8
  TOP w0.254: U10.28 21.75,4.73 v1(21.34,4.32)
  LAYER3 w0.254: v1(21.34,4.32) 21.34,4.06 21.08,3.81 17.4,3.81 17.14,4.06 v1(17.14,4.57)
  BOTTOM w0.127: U7.15 17.04,8.15
  BOTTOM w0.203: R11.2 17.25,6.22 17.04,6.43 17.04,8.15
  BOTTOM w0.254: v1(17.14,4.57) 17.14,5.49 R11.2
UNNAMED_1_1210IND_I97_A: length 11.3
  TOP w0.381: 6.98,6.02 6.98,7.11 7.62,7.75 8.38,7.75 9.03,8.4 9.03,9.03 8.41,9.65 U8.5 ; 6.98,6.02 6.98,5.25 8.51,3.72 L1.1 ; 6.98,6.02 6.85,6.15 J1.1
UNNAMED_1_HEADERS_I279_IN1: length 25
  TOP w0.254: 43.69,14.99 v1(43.69,12.12) ; 43.69,14.99 43.81,15.11 44.83,15.11 45.09,15.37 U11.3 ; 43.69,14.99 43.69,16.38 43.96,16.65 U11.1
  BOTTOM w0.254: J2.2 J2.1 54.74,16 50.85,12.12 v1(43.69,12.12)
UNNAMED_1_HEADERS_I281_IN1: length 40.4
  TOP w0.254: U5.2 36.84,5.96 36.58,6.22 35.81,6.22 v1(35.43,6.6) ; R25.2 50.04,12.12 50.8,11.35 50.8,9.65 ; 50.8,9.65 59.82,9.65 60.58,10.41 60.58,12.07 J2.4 J2.3 ; 50.8,9.65 v1(50.8,7.24)
  LAYER2 w0.254: v1(50.8,7.24) 50.16,6.6 v1(35.43,6.6)
UNNAMED_1_HEADERS_I283_IN1: length 7.7
  TOP w0.254: R28.2 55.56,10.79 55.69,10.92 J2.5 J2.6
  BOTTOM w0.381: R21.2 56.18,10.46 J2.5
UNNAMED_1_HEADERS_I285_IN1: length 9.4
  TOP w0.254: R29.2 J2.7
  BOTTOM w0.254: J2.8 J2.7
  BOTTOM w0.381: R30.1 54.76,8.18 R21.1 56.44,8.59 J2.7
UNNAMED_1_IP4220CZ6_I167_4: length 15.7
  TOP w0.254: U8.4 6.38,10.6 6.33,10.65 J1.3
  BOTTOM w0.127: U7.24 15.9,12.29 15.9,12.29
  BOTTOM w0.254: 15.9,12.29 15.27,12.29 13.21,14.35 8.68,14.35 v1(5.21,10.67)
UNNAMED_1_IP4220CZ6_I167_6: length 15.4
  TOP w0.254: U8.6 6.38,8.7 6.33,8.65 J1.2
  BOTTOM w0.127: U7.23 15.9,11.79
  BOTTOM w0.254: 15.9,11.79 15,11.79 13.97,12.83 10.41,12.83 6.24,8.65 v1(5.21,8.64)
UNNAMED_1_ISL23328_I318_9: length 6.5
  TOP w0.127: U4.2 31.65,8.64
  TOP w0.254: 31.65,8.64 v1(31.65,9.75)
  BOTTOM w0.203: U1.9 30.64,13.63 30.35,13.34 30.35,12.19 31.65,10.89 v1(31.65,9.75)
UNNAMED_1_ISL23328_I318_12: length 14.9
  TOP w0.127: U4.1 32.3,8.64
  TOP w0.254: 32.3,8.64 v1(34.04,8.64)
  LAYER2 w0.254: v1(34.04,8.64) 34.04,9.65 35.69,11.3 35.69,13.34 34.1,14.93 30.54,14.93 v1(30.23,15.24)
  BOTTOM w0.203: U1.12 30.64,14.82 v1(30.23,15.24)
UNNAMED_1_ISL26104_I314_10: length 2.5
  TOP w0.254: C2.1 16.23,13.56 15.9,13.23 U10.10
UNNAMED_1_ISL28233_I317_1: length 3
  TOP w0.254: U3.2 U3.1 29.04,15.8 29.25,16 29.74,16 30,16.26 R14.2
UNNAMED_1_ISL28233_I317_3: length 15.5
  TOP w0.127: U4.6 29.05,8.64
  TOP w0.254: 29.05,8.64 29.05,7.21 28.7,6.86 27.56,6.86 26.42,8 26.42,9.65 25.53,10.54 25.53,12.44 25.53,12.45 25.53,15.11 26.42,16 27.54,16 27.74,15.8 U3.3
UNNAMED_1_ISL28233_I317_5: length 7.2
  TOP w0.127: U4.3 31,8.64
  TOP w0.254: 31,8.64 31,9.46 30.88,9.59 30.16,9.59 30.16,9.59 28.1,9.59 27.09,10.6 U3.5
UNNAMED_1_ISL28233_I317_6: length 2.3
  TOP w0.254: U3.7 U3.6 27.74,11.87 27.99,11.62 R15.1
UNNAMED_1_ISL28634_I315_4: length 9.4
  TOP w0.254: U4.4 30.35,6.86 30.61,6.6 34.16,6.6 34.67,7.11 36.24,7.11 36.89,6.46 U5.1
UNNAMED_1_ISL28634_I315_5: length 17.2
  TOP w0.127: U4.5 29.7,8.64
  TOP w0.254: v1(29.72,6.86) 29.72,7.8 29.7,7.81 29.7,8.64 ; U5.14 v1(41.9,5.96)
  LAYER3 w0.254: v1(41.9,5.96) 39.62,3.68 32.89,3.68 v1(29.72,6.86)
UNNAMED_1_ISL43840_I225_15: length 13
  TOP w0.127: 36.7,5.49 36.73,5.46 36.79,5.46
  TOP w0.254: v1(41.91,7.49) 41.65,7.49 41.02,6.87 U5.15 ; v1(34.8,4.83) 34.8,5.21 35.08,5.49 R6.2 36.77,5.49 36.79,5.46 U5.3
  LAYER3 w0.254: v1(41.91,7.49) 37.46,7.49 v1(34.8,4.83)
UNNAMED_1_MMSD4148T1_I291_AN: length 20.3
  TOP w0.254: v1(51.69,10.79) R28.1 52.93,11.6 53.97,12.64 D6.2 D4.1 ; U5.16 40.59,7.24 41.4,8.05 v1(41.4,9.91)
  LAYER2 w0.254: v1(51.69,10.79) 44.32,10.79 43.43,9.91 v1(41.4,9.91)
UNNAMED_1_MMSD4148T1_I302_CAT: length 24.5
  TOP w0.127: 37.59,7.55 37.9,7.24
  TOP w0.254: U5.20 37.84,7.24 37.59,7.48 v1(37.59,8.51) ; R29.1 52.93,8.15 53.85,7.24 D2.1 52.7,5.89 ; v1(52.7,6.73) 52.7,5.89 ; 52.7,5.89 D5.2
  LAYER2 w0.254: v1(37.59,8.51) 38.23,9.14 49.91,9.14 v1(52.7,6.73)
UNNAMED_1_R5F10JBCANA_I307_1: length 9.2
  BOTTOM w0.127: U7.1 20.68,12.29 20.68,12.29
  BOTTOM w0.254: P1.1 16.76,16.13 19.68,16.13 20.68,15.14 20.68,12.29
UNNAMED_1_R5F10JBCANA_I307_2: length 12.3
  TOP w0.254: v1(22.45,14.07) 23.04,14.07 23.16,13.94 R8.2
  BOTTOM w0.127: U7.2 20.68,11.79 ; 21.85,14.07 21.82,14.1
  BOTTOM w0.254: 20.68,11.79 21.5,11.79 21.82,12.12 21.82,16.15 20.45,17.53 P2.1 ; v1(22.45,14.07) 21.85,14.07
UNNAMED_1_R5F10JBCANA_I307_3: length 4.9
  BOTTOM w0.127: U7.3 20.68,11.29
  BOTTOM w0.254: 20.68,11.29 22.21,11.29 24.13,13.21 R9.2
UNNAMED_1_R5F10JBCANA_I307_5: length 2.8
  BOTTOM w0.127: U7.5 20.68,10.29
  BOTTOM w0.254: R10.2 22.86,10.03 22.61,10.29 20.68,10.29
UNNAMED_1_R5F10JBCANA_I307_6: length 2.9
  BOTTOM w0.127: 20.68,9.79 U7.6
  BOTTOM w0.254: C12.1 22.43,8.38 22.43,9.12 21.77,9.78 21.72,9.79 20.68,9.79
UNNAMED_1_R5F10JBCANA_I307_12: length 2.8
  BOTTOM w0.127: U7.12 18.54,8.15
  BOTTOM w0.203: R11.1 18.31,6.22 18.67,6.58 18.67,7.75 18.54,7.88 18.54,8.15
UNNAMED_1_R5F10JBCANA_I307_22: length 4.7
  BOTTOM w0.127: U7.22 15.9,11.29
  BOTTOM w0.254: 15.9,11.29 14.89,11.29 14.01,10.41 C11.2 13.26,11.28 13.23,11.3 R7.2
UNNAMED_1_SMCAP_I18_B: length 2.7
  TOP w0.254: U10.9 16.55,12.97 17.3,13.72 C2.2
UNNAMED_1_SMCAP_I21_A: length 8
  TOP w0.254: D1.1 23.19,4.6 21.92,3.33 R3.1 20.57,3.33 ; 20.57,3.33 20.57,3.76 20.7,3.89 20.7,4.89 20.45,5.14 U10.26 ; 20.57,3.33 20.19,3.33 20.17,3.35 C8.1
UNNAMED_1_SMCAP_I197_A: length 14.5
  TOP w0.254: v1(16.26,4.57) 16.55,4.87 U10.20
  LAYER3 w0.254: v1(16.26,4.57) 16.26,3.68 17.53,2.41 21.6,2.41 v1(23.11,1.02)
  BOTTOM w0.254: R2.2 26.42,1.12 26.39,1.14 C4.1 23.75,1.14 23.62,1.02 v1(23.11,1.02)
UNNAMED_1_SMCAP_I319_A: length 15
  TOP w0.127: C29.1 C28.1
  TOP w0.254: C29.1 15.27,15.24 15.25,15.22 U10.11 15.25,10.53 15.75,10.03 R4.2
UNNAMED_1_SMCAP_I319_B: length 15.5
  TOP w0.254: R5.2 22.99,8.38 22.41,8.96 15.55,8.96 14.6,9.91 U10.12 14.6,13.11 14.5,13.21 C30.1 14.5,14.81 14.2,15.11 C29.2
UNNAMED_1_SMCAP_I323_A: length 24.9
  TOP w0.127: U4.11 30.35,2.79
  TOP w0.254: 30.35,2.79 30.35,1.4 30.48,1.27 v1(32.38,1.27) ; v1(41.66,11.94) 42.93,13.21 C23.1 41.63,14.71 41.4,14.48 U6.6 40.64,14.48
  LAYER2 w0.254: v1(32.38,1.27) 32.38,4.57 39.75,11.94 v1(41.66,11.94)
UNNAMED_1_SMCAP_I358_A: length 9.3
  BOTTOM w0.127: U7.4 20.68,10.79 ; 26.92,13.23 26.95,13.25
  BOTTOM w0.254: 26.95,13.25 C9.1 ; 26.92,13.23 Y1.1 23.72,12.03 22.48,10.79 20.68,10.79
UNNAMED_1_SMCAP_I359_A: length 6.1
  BOTTOM w0.254: 24.41,10.03 26.12,10.03 26.92,9.23 Y1.2 26.92,6.69 26.95,6.67 C13.1
UNNAMED_1_SMLED_I99_A: length 2.1
  TOP w0.381: R17.1 8.17,14.44 D3.1
UNNAMED_1_SMRES_I15_B: length 2.2
  TOP w0.254: R1.2 20.32,13.53 20.45,13.39 U10.3
UNNAMED_1_SMRES_I227_A: length 8.7
  TOP w0.127: U4.10 29.7,2.79
  TOP w0.254: 29.7,2.79 29.7,3.63 28.64,4.7 27.18,4.7 24.41,7.47 R5.1
UNNAMED_1_SMRES_I228_A: length 11.2
  TOP w0.127: U4.12 31,2.79
  TOP w0.254: 31,2.79 31,3.62 31,3.79 29.08,5.72 27.56,5.72 25.53,7.75 25.53,9.4 24.89,10.03 24.41,10.03
UNNAMED_1_SMRES_I262_A: length 2.2
  TOP w0.254: R18.1 R19.2
UNNAMED_1_SMRES_I262_B: length 3.4
  TOP w0.254: R16.1 43.85,10.24 44.65,11.03 45.11,11.03 46.19,12.12 R18.2
UNNAMED_1_SMRES_I264_A: length 8.2
  TOP w0.254: U5.12 41.79,4.96 42.55,5.72 42.55,7.07 43.52,8.05 R22.2 43.85,8.05 44.79,7.11 45.25,7.11 46.19,6.17 R19.1
UNNAMED_1_SMRES_I265_A: length 2.2
  TOP w0.254: R22.1 R23.2
UNNAMED_1_SMRES_I266_A: length 3.4
  TOP w0.254: R23.1 43.85,2.11 44.67,2.92 45.12,2.92 46.19,3.99 R24.2
UNNAMED_1_SMRES_I268_A: length 2.2
  TOP w0.254: R25.1 R26.2
UNNAMED_1_SMRES_I269_A: length 2.2
  TOP w0.254: R26.1 R27.2
VREF: length 4.5
  BOTTOM w0.254: R2.1 C5.1 28.04,3.4 29.28,4.65 U2.2

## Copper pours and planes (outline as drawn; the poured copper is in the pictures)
GND on TOP: 0,15.75 3.56,19.3 59.56,19.3 61.47,17.4 61.47,1.91 59.56,0 3.56,0 0,3.56 ; 9 cut-outs
GND on BOTTOM: 0,15.75 3.56,19.3 59.56,19.3 61.47,17.4 61.47,1.91 59.56,0 3.56,0 0,3.56 ; 6 cut-outs
GND on LAYER2, LAYER3: 0,15.75 3.56,19.3 59.56,19.3 61.47,17.4 61.47,1.91 59.56,0 3.56,0 0,3.56

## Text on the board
BOTTOM: SOLDERMASK TOP | bottom
Ref Des/Silkscreen Bottom: REV B | RTKA-BDGSTKEV1Z | silkb
User.Comments: 10.THIS IS A ROHS BOARD.  USE IMERSION GOLD PLATING | smaskt | smaskb
Board Geometry/Outline: 03/21/2019 | SOLDERMASK BOT | REV B | RENESAS | RTKA-BDGSTKEV1Z
TOP: top
Ref Des/Silkscreen Top: silkt
LAYER2: layer2
LAYER3: layer 3
DIMENSION: 0 | layer3.art | layer2.art | 2 places | x 45 | TOP (COMPONENT SIDE) | LAYER STRUCTURE IS AS FOLLOWS: | top.art | smask.art | silkb.art | silkt.art | bottom.art | smaskt.art | " | 0.41"
DISPLAY_TOP: FIGURE | SIZE | 10.0 | 20.0 | 31.0 | 41.0 | 91.0 | 47.0 | DRILL CHART: TOP to BOTTOM | ALL UNITS ARE IN MILS | PLATED | NON-PLATED | QTY | 96 | 1 | 2 | 12
